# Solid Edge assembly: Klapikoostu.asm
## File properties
Author: Türk
Template: Iso Assembly.asm
Last saved by: Türk
Revision: 9
Application: Solid Edge
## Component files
Klapipuks.par
Klapp.par
Klapi vedru.par
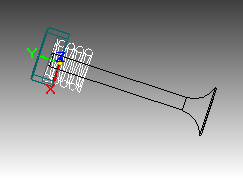
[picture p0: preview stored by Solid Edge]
